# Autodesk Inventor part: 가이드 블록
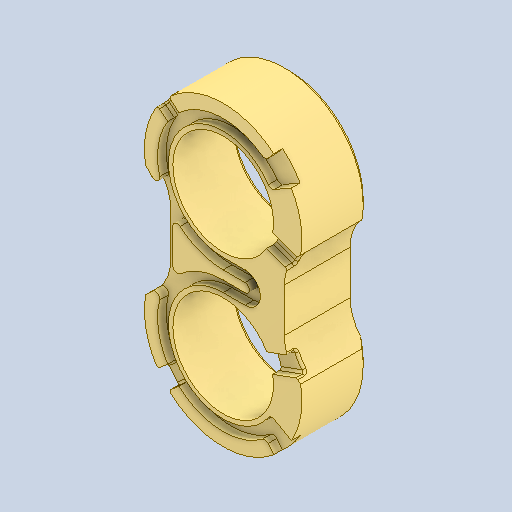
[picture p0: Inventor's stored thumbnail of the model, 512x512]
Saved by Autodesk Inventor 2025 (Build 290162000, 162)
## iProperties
Created: 2026-08
Part Number: 가이드 블록
Material: 일반
Document SubType Name: Modeling
Designer: KDI
Density: 1 g/cm^3
Appearance: 기본값
Author: jhkim
Sending System: Autodesk Inventor 2027
Preprocessor: ST-DEVELOPER v20.1
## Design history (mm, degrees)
feature "솔리드1"
node "솔리드2"
